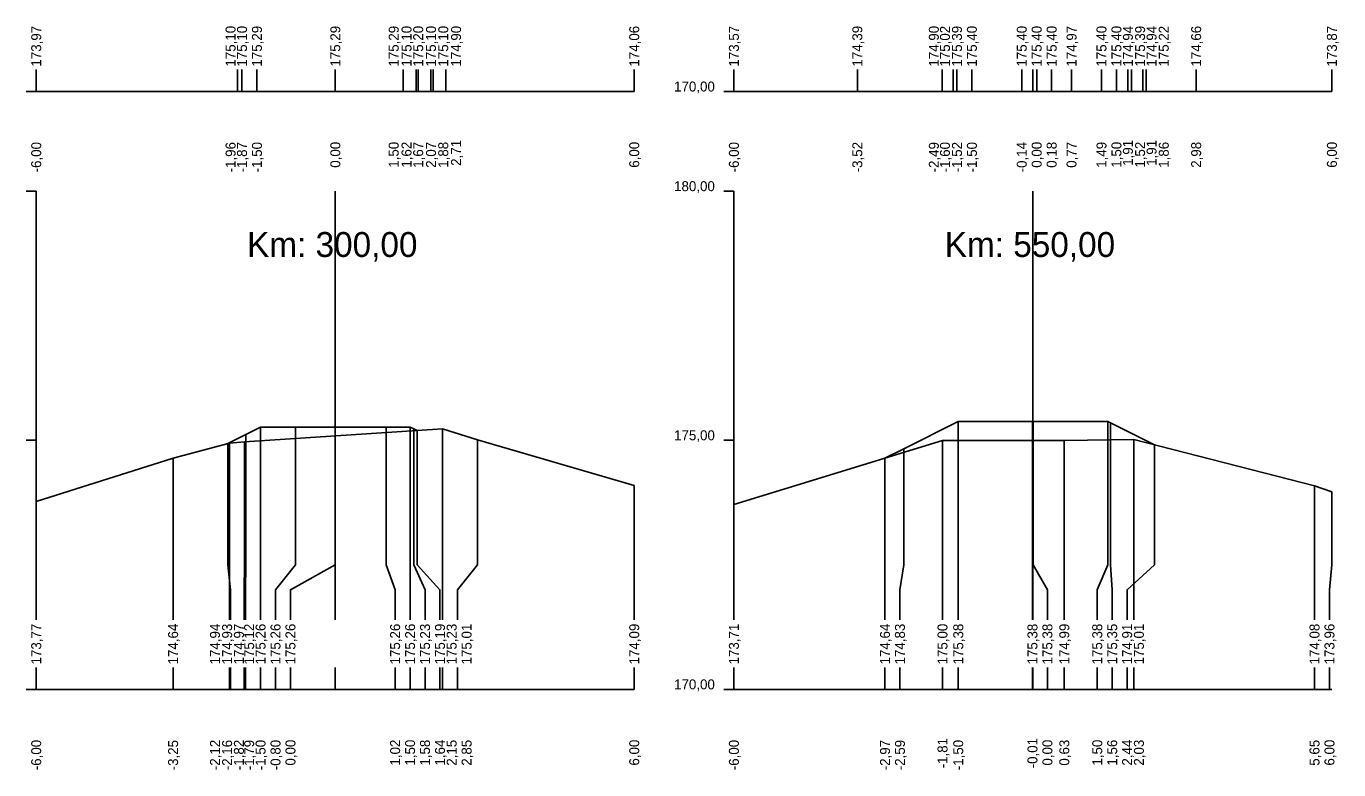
# Model space of a CAD drawing. Extents: x -614174 to -599765, y -1185887 to -1181080.
# Drawn here: x -608795.02 to -608768.69, y -1184504.1 to -1184489.18 of the extents above; entities that cross this region are included whole.
import ezdxf

# ---------------------------------------------------------------- set-up
doc = ezdxf.new("R2010")
doc.units = 0
for name, color, linetype in [('11', 7, 'Continuous'), ('16', 7, 'Continuous'), ('21', 7, 'Continuous'), ('28', 7, 'Continuous'), ('59', 7, 'Continuous'), ('8', 7, 'Continuous')]:
    doc.layers.add(name, color=color, linetype=linetype)

msp = doc.modelspace()

# ---------------------------------------------------------------- linework, layer by layer
for points in [[(-608777.793, -1184497.845), (-608777.416, -1184497.657), (-608776.323, -1184497.111), (-608774.834, -1184497.111), (-608774.823, -1184497.111), (-608773.324, -1184497.111), (-608773.267, -1184497.139), (-608772.388, -1184497.578)], [(-608776.323, -1184497.111), (-608776.323, -1184497.111), (-608776.323, -1184497.111)], [(-608774.823, -1184497.111), (-608774.823, -1184497.111), (-608774.823, -1184497.111)], [(-608773.324, -1184497.111), (-608773.324, -1184497.111), (-608773.324, -1184497.111)], [(-608794.825, -1184498.718), (-608792.078, -1184497.847), (-608790.949, -1184497.544), (-608790.648, -1184497.517), (-608786.674, -1184497.261), (-608785.972, -1184497.478), (-608782.825, -1184498.394)], [(-608790.982, -1184497.553), (-608790.616, -1184497.37), (-608790.323, -1184497.223), (-608789.624, -1184497.223), (-608788.823, -1184497.223), (-608787.803, -1184497.223), (-608787.323, -1184497.223), (-608787.248, -1184497.261), (-608787.182, -1184497.294)], [(-608790.323, -1184497.223), (-608790.323, -1184497.223), (-608790.323, -1184497.223)], [(-608788.823, -1184497.223), (-608788.823, -1184497.223), (-608788.823, -1184497.223)], [(-608787.323, -1184497.223), (-608787.323, -1184497.223), (-608787.323, -1184497.223)], [(-608790.982, -1184497.553), (-608790.982, -1184497.553), (-608790.982, -1184497.553)], [(-608780.825, -1184498.778), (-608776.639, -1184497.491), (-608774.195, -1184497.494), (-608772.797, -1184497.473), (-608769.174, -1184498.405), (-608768.825, -1184498.523)], [(-608777.792, -1184497.845), (-608777.793, -1184497.845), (-608777.793, -1184497.845)]]:
    msp.add_lwpolyline(points)
at = {"layer": '11'}
for points in [[(-608794.825, -1184490.047), (-608794.825, -1184490.487)], [(-608790.788, -1184490.047), (-608790.788, -1184490.487)], [(-608790.696, -1184490.047), (-608790.696, -1184490.487)], [(-608790.396, -1184490.047), (-608790.396, -1184490.487)], [(-608788.823, -1184490.047), (-608788.823, -1184490.487)], [(-608787.46, -1184490.047), (-608787.46, -1184490.487)], [(-608787.203, -1184490.047), (-608787.203, -1184490.487)], [(-608787.16, -1184490.047), (-608787.16, -1184490.487)], [(-608786.903, -1184490.047), (-608786.903, -1184490.487)], [(-608786.86, -1184490.047), (-608786.86, -1184490.487)], [(-608786.603, -1184490.047), (-608786.603, -1184490.487)], [(-608782.825, -1184490.047), (-608782.825, -1184490.487)], [(-608780.825, -1184490.047), (-608780.825, -1184490.487)], [(-608778.348, -1184490.047), (-608778.348, -1184490.487)], [(-608776.649, -1184490.047), (-608776.649, -1184490.487)], [(-608776.426, -1184490.047), (-608776.426, -1184490.487)], [(-608776.349, -1184490.047), (-608776.349, -1184490.487)], [(-608776.049, -1184490.047), (-608776.049, -1184490.487)], [(-608775.049, -1184490.047), (-608775.049, -1184490.487)], [(-608774.749, -1184490.047), (-608774.749, -1184490.487)], [(-608774.449, -1184490.047), (-608774.449, -1184490.487)], [(-608774.05, -1184490.047), (-608774.05, -1184490.487)], [(-608773.449, -1184490.047), (-608773.449, -1184490.487)], [(-608773.149, -1184490.047), (-608773.149, -1184490.487)], [(-608772.919, -1184490.047), (-608772.919, -1184490.487)], [(-608772.849, -1184490.047), (-608772.849, -1184490.487)], [(-608772.619, -1184490.047), (-608772.619, -1184490.487)], [(-608772.549, -1184490.047), (-608772.549, -1184490.487)], [(-608771.549, -1184490.047), (-608771.549, -1184490.487)], [(-608768.825, -1184490.047), (-608768.825, -1184490.487)], [(-608776.323, -1184497.111), (-608776.323, -1184499.987), (-608776.323, -1184500.487), (-608776.323, -1184501.089)], [(-608774.834, -1184497.111), (-608774.834, -1184499.987), (-608774.834, -1184500.487), (-608774.834, -1184501.089)], [(-608774.823, -1184497.111), (-608774.823, -1184499.987), (-608774.534, -1184500.487), (-608774.534, -1184501.089)], [(-608773.324, -1184497.111), (-608773.324, -1184499.987), (-608773.534, -1184500.487), (-608773.534, -1184501.089)], [(-608773.267, -1184497.139), (-608773.267, -1184499.987), (-608773.234, -1184500.487), (-608773.234, -1184501.089)], [(-608790.616, -1184497.37), (-608790.616, -1184499.987), (-608790.623, -1184500.487), (-608790.623, -1184501.089)], [(-608790.323, -1184497.223), (-608790.323, -1184499.987), (-608790.323, -1184500.487), (-608790.323, -1184501.089)], [(-608789.624, -1184497.223), (-608789.624, -1184499.987), (-608790.023, -1184500.487), (-608790.023, -1184501.089)], [(-608788.823, -1184497.223), (-608788.823, -1184499.987), (-608789.723, -1184500.487), (-608789.723, -1184501.089)], [(-608787.803, -1184497.223), (-608787.803, -1184499.987), (-608787.623, -1184500.487), (-608787.623, -1184501.089)], [(-608787.323, -1184497.223), (-608787.323, -1184499.987), (-608787.323, -1184500.487), (-608787.323, -1184501.089)], [(-608787.248, -1184497.261), (-608787.248, -1184499.987), (-608787.023, -1184500.487), (-608787.023, -1184501.089)], [(-608787.182, -1184497.294), (-608787.182, -1184499.987), (-608786.723, -1184500.487), (-608786.723, -1184501.089)], [(-608786.674, -1184497.261), (-608786.674, -1184499.987), (-608786.674, -1184500.487), (-608786.674, -1184501.089)], [(-608790.982, -1184497.553), (-608790.982, -1184499.987), (-608790.923, -1184500.487), (-608790.923, -1184501.089)], [(-608790.949, -1184497.544), (-608790.949, -1184499.987), (-608790.949, -1184500.487), (-608790.949, -1184501.089)], [(-608790.648, -1184497.517), (-608790.648, -1184499.987), (-608790.649, -1184500.487), (-608790.649, -1184501.089)], [(-608785.972, -1184497.478), (-608785.972, -1184499.987), (-608786.374, -1184500.487), (-608786.374, -1184501.089)], [(-608777.416, -1184497.657), (-608777.416, -1184499.987), (-608777.493, -1184500.487), (-608777.493, -1184501.089)], [(-608776.639, -1184497.491), (-608776.639, -1184499.987), (-608776.639, -1184500.487), (-608776.639, -1184501.089)], [(-608774.195, -1184497.494), (-608774.195, -1184499.987), (-608774.195, -1184500.487), (-608774.195, -1184501.089)], [(-608772.388, -1184497.578), (-608772.388, -1184499.987), (-608772.934, -1184500.487), (-608772.934, -1184501.089)], [(-608772.797, -1184497.473), (-608772.797, -1184499.987), (-608772.797, -1184500.487), (-608772.797, -1184501.089)], [(-608792.078, -1184497.847), (-608792.078, -1184499.987), (-608792.078, -1184500.487), (-608792.078, -1184501.089)], [(-608777.793, -1184497.845), (-608777.793, -1184499.987), (-608777.793, -1184500.487), (-608777.793, -1184501.089)], [(-608782.825, -1184498.394), (-608782.825, -1184499.987), (-608782.825, -1184500.487), (-608782.825, -1184501.089)], [(-608769.174, -1184498.405), (-608769.174, -1184499.987), (-608769.174, -1184500.487), (-608769.174, -1184501.089)], [(-608794.825, -1184498.718), (-608794.825, -1184499.987), (-608794.825, -1184500.487), (-608794.825, -1184501.089)], [(-608768.825, -1184498.523), (-608768.825, -1184499.987), (-608768.874, -1184500.487), (-608768.874, -1184501.089)], [(-608780.825, -1184498.778), (-608780.825, -1184499.987), (-608780.825, -1184500.487), (-608780.825, -1184501.089)], [(-608794.825, -1184502.047), (-608794.825, -1184502.487)], [(-608792.078, -1184502.047), (-608792.078, -1184502.487)], [(-608790.949, -1184502.047), (-608790.949, -1184502.487)], [(-608790.923, -1184502.047), (-608790.923, -1184502.487)], [(-608790.649, -1184502.047), (-608790.649, -1184502.487)], [(-608790.623, -1184502.047), (-608790.623, -1184502.487)], [(-608790.323, -1184502.047), (-608790.323, -1184502.487)], [(-608790.023, -1184502.047), (-608790.023, -1184502.487)], [(-608789.723, -1184502.047), (-608789.723, -1184502.487)], [(-608787.623, -1184502.047), (-608787.623, -1184502.487)], [(-608787.323, -1184502.047), (-608787.323, -1184502.487)], [(-608787.023, -1184502.047), (-608787.023, -1184502.487)], [(-608786.723, -1184502.047), (-608786.723, -1184502.487)], [(-608786.674, -1184502.047), (-608786.674, -1184502.487)], [(-608786.374, -1184502.047), (-608786.374, -1184502.487)], [(-608782.825, -1184502.047), (-608782.825, -1184502.487)], [(-608780.825, -1184502.047), (-608780.825, -1184502.487)], [(-608777.793, -1184502.047), (-608777.793, -1184502.487)], [(-608777.493, -1184502.047), (-608777.493, -1184502.487)], [(-608776.639, -1184502.047), (-608776.639, -1184502.487)], [(-608776.323, -1184502.047), (-608776.323, -1184502.487)], [(-608774.834, -1184502.047), (-608774.834, -1184502.487)], [(-608774.534, -1184502.047), (-608774.534, -1184502.487)], [(-608774.195, -1184502.047), (-608774.195, -1184502.487)], [(-608773.534, -1184502.047), (-608773.534, -1184502.487)], [(-608773.234, -1184502.047), (-608773.234, -1184502.487)], [(-608772.934, -1184502.047), (-608772.934, -1184502.487)], [(-608772.797, -1184502.047), (-608772.797, -1184502.487)], [(-608769.174, -1184502.047), (-608769.174, -1184502.487)], [(-608768.874, -1184502.047), (-608768.874, -1184502.487)]]:
    msp.add_lwpolyline(points, dxfattribs=at)
at = {"layer": '16'}
for p, q in [((-608794.825, -1184490.487), (-608782.825, -1184490.487)), ((-608780.825, -1184490.487), (-608768.825, -1184490.487)), ((-608794.825, -1184502.487), (-608782.825, -1184502.487)), ((-608780.825, -1184502.487), (-608768.825, -1184502.487))]:
    msp.add_line(p, q, dxfattribs=at)
for points in [[(-608787.182, -1184497.294), (-608787.182, -1184497.294), (-608787.182, -1184497.294)], [(-608772.389, -1184497.578), (-608772.388, -1184497.578), (-608772.388, -1184497.578)]]:
    msp.add_lwpolyline(points, dxfattribs=at)
at = {"layer": '21'}
for p, q in [((-608795.025, -1184490.487), (-608794.825, -1184490.487)), ((-608781.025, -1184490.487), (-608780.825, -1184490.487)), ((-608795.025, -1184492.487), (-608794.825, -1184492.487)), ((-608781.025, -1184492.487), (-608780.825, -1184492.487)), ((-608795.025, -1184497.487), (-608794.825, -1184497.487)), ((-608781.025, -1184497.487), (-608780.825, -1184497.487)), ((-608795.025, -1184502.487), (-608794.825, -1184502.487)), ((-608781.025, -1184502.487), (-608780.825, -1184502.487))]:
    msp.add_line(p, q, dxfattribs=at)
at = {"layer": '28'}
for p, q in [((-608788.825, -1184490.487), (-608788.825, -1184490.047)), ((-608774.825, -1184490.487), (-608774.825, -1184490.047)), ((-608788.825, -1184501.089), (-608788.825, -1184492.487)), ((-608774.825, -1184501.089), (-608774.825, -1184492.487)), ((-608788.825, -1184502.487), (-608788.825, -1184502.047)), ((-608774.825, -1184502.487), (-608774.825, -1184502.047))]:
    msp.add_line(p, q, dxfattribs=at)
at = {"layer": '8'}
for p, q in [((-608794.825, -1184490.487), (-608794.825, -1184490.047)), ((-608780.825, -1184490.487), (-608780.825, -1184490.047)), ((-608794.825, -1184501.089), (-608794.825, -1184492.487)), ((-608780.825, -1184501.089), (-608780.825, -1184492.487)), ((-608794.825, -1184502.487), (-608794.825, -1184502.047)), ((-608780.825, -1184502.487), (-608780.825, -1184502.047))]:
    msp.add_line(p, q, dxfattribs=at)

# ---------------------------------------------------------------- texts
at = {"layer": '16'}
for s, p in [('173,97', (-608794.725, -1184489.987)), ('175,10', (-608790.825, -1184489.987)), ('175,10', (-608790.596, -1184489.987)), ('175,29', (-608790.296, -1184489.987)), ('175,29', (-608788.723, -1184489.987)), ('175,29', (-608787.551, -1184489.987)), ('175,10', (-608787.294, -1184489.987)), ('175,20', (-608787.06, -1184489.987)), ('175,10', (-608786.803, -1184489.987)), ('175,10', (-608786.557, -1184489.987)), ('174,90', (-608786.3, -1184489.987)), ('174,06', (-608782.725, -1184489.987)), ('173,57', (-608780.725, -1184489.987)), ('174,39', (-608778.248, -1184489.987)), ('174,90', (-608776.713, -1184489.987)), ('175,02', (-608776.49, -1184489.987)), ('175,39', (-608776.249, -1184489.987)), ('175,40', (-608775.949, -1184489.987)), ('175,40', (-608774.949, -1184489.987)), ('175,40', (-608774.649, -1184489.987)), ('175,40', (-608774.349, -1184489.987)), ('174,97', (-608773.95, -1184489.987)), ('175,40', (-608773.349, -1184489.987)), ('175,40', (-608773.049, -1184489.987)), ('174,94', (-608772.819, -1184489.987)), ('175,39', (-608772.574, -1184489.987)), ('174,94', (-608772.344, -1184489.987)), ('175,22', (-608772.099, -1184489.987)), ('174,66', (-608771.449, -1184489.987)), ('173,87', (-608768.725, -1184489.987)), ('173,77', (-608794.725, -1184501.987)), ('174,64', (-608791.978, -1184501.987)), ('174,94', (-608791.138, -1184501.987)), ('174,93', (-608790.894, -1184501.987)), ('174,97', (-608790.658, -1184501.987)), ('175,12', (-608790.452, -1184501.987)), ('175,26', (-608790.223, -1184501.987)), ('175,26', (-608789.923, -1184501.987)), ('175,26', (-608789.623, -1184501.987)), ('175,26', (-608787.523, -1184501.987)), ('175,26', (-608787.223, -1184501.987)), ('175,23', (-608786.923, -1184501.987)), ('175,19', (-608786.623, -1184501.987)), ('175,23', (-608786.389, -1184501.987)), ('175,01', (-608786.089, -1184501.987)), ('174,09', (-608782.725, -1184501.987)), ('173,71', (-608780.725, -1184501.987)), ('174,64', (-608777.693, -1184501.987)), ('174,83', (-608777.393, -1184501.987)), ('175,00', (-608776.539, -1184501.987)), ('175,38', (-608776.223, -1184501.987)), ('175,38', (-608774.734, -1184501.987)), ('175,38', (-608774.434, -1184501.987)), ('174,99', (-608774.095, -1184501.987)), ('175,38', (-608773.434, -1184501.987)), ('175,35', (-608773.134, -1184501.987)), ('174,91', (-608772.834, -1184501.987)), ('175,01', (-608772.598, -1184501.987)), ('174,08', (-608769.074, -1184501.987)), ('173,96', (-608768.774, -1184501.987))]:
    msp.add_text(s, height=0.2, rotation=90, dxfattribs=at).set_placement(p)
at = {"layer": '21'}
for s, p in [('170,00', (-608782.025, -1184490.487)), ('180,00', (-608782.025, -1184492.487)), ('175,00', (-608782.025, -1184497.487)), ('170,00', (-608782.025, -1184502.487))]:
    msp.add_text(s, height=0.2, dxfattribs=at).set_placement(p)
at = {"layer": '28'}
for s, p in [('Km: 300,00', (-608790.594, -1184493.808)), ('Km: 550,00', (-608776.594, -1184493.808))]:
    msp.add_text(s, height=0.5, dxfattribs=at).set_placement(p)
at = {"layer": '59'}
for s, p in [('-6,00', (-608794.725, -1184492.11)), ('-1,96', (-608790.825, -1184492.111)), ('-1,87', (-608790.596, -1184492.111)), ('-1,50', (-608790.296, -1184492.11)), ('0,00', (-608788.723, -1184492.017)), ('1,50', (-608787.551, -1184492.017)), ('1,62', (-608787.294, -1184492.016)), ('1,67', (-608787.06, -1184492.018)), ('2,07', (-608786.803, -1184492.018)), ('1,88', (-608786.557, -1184492.018)), ('2,71', (-608786.3, -1184491.979)), ('6,00', (-608782.725, -1184492.017)), ('-6,00', (-608780.725, -1184492.11)), ('-3,52', (-608778.248, -1184492.109)), ('-2,49', (-608776.713, -1184492.111)), ('-1,60', (-608776.49, -1184492.11)), ('-1,52', (-608776.249, -1184492.109)), ('-1,50', (-608775.949, -1184492.11)), ('-0,14', (-608774.949, -1184492.11)), ('0,00', (-608774.649, -1184492.017)), ('0,18', (-608774.349, -1184492.018)), ('0,77', (-608773.95, -1184492.018)), ('1,49', (-608773.349, -1184492.018)), ('1,50', (-608773.049, -1184492.017)), ('1,91', (-608772.819, -1184491.979)), ('1,52', (-608772.574, -1184492.016)), ('1,91', (-608772.344, -1184491.979)), ('1,86', (-608772.099, -1184492.018)), ('2,98', (-608771.449, -1184492.018)), ('6,00', (-608768.725, -1184492.017)), ('0,00', (-608789.623, -1184504.017)), ('1,02', (-608787.523, -1184504.016)), ('1,50', (-608787.223, -1184504.017)), ('1,64', (-608786.623, -1184504.017)), ('6,00', (-608782.725, -1184504.017)), ('-1,81', (-608776.539, -1184504.072)), ('-0,01', (-608774.734, -1184504.072)), ('0,00', (-608774.434, -1184504.017)), ('1,50', (-608773.434, -1184504.017)), ('2,44', (-608772.834, -1184504.017)), ('6,00', (-608768.774, -1184504.017)), ('-6,00', (-608794.725, -1184504.11)), ('-3,25', (-608791.978, -1184504.113)), ('-2,12', (-608791.138, -1184504.109)), ('-2,16', (-608790.894, -1184504.111)), ('-1,82', (-608790.658, -1184504.109)), ('-1,79', (-608790.452, -1184504.111)), ('-1,50', (-608790.223, -1184504.11)), ('-0,80', (-608789.923, -1184504.11)), ('1,58', (-608786.923, -1184504.018)), ('2,15', (-608786.389, -1184504.02)), ('2,85', (-608786.089, -1184504.02)), ('-6,00', (-608780.725, -1184504.11)), ('-2,97', (-608777.693, -1184504.111)), ('-2,59', (-608777.393, -1184504.111)), ('-1,50', (-608776.223, -1184504.11)), ('0,63', (-608774.095, -1184504.018)), ('1,56', (-608773.134, -1184504.018)), ('2,03', (-608772.598, -1184504.018)), ('5,65', (-608769.074, -1184504.02))]:
    msp.add_text(s, height=0.2, rotation=90, dxfattribs=at).set_placement(p)

doc.saveas('drawing.dxf')
